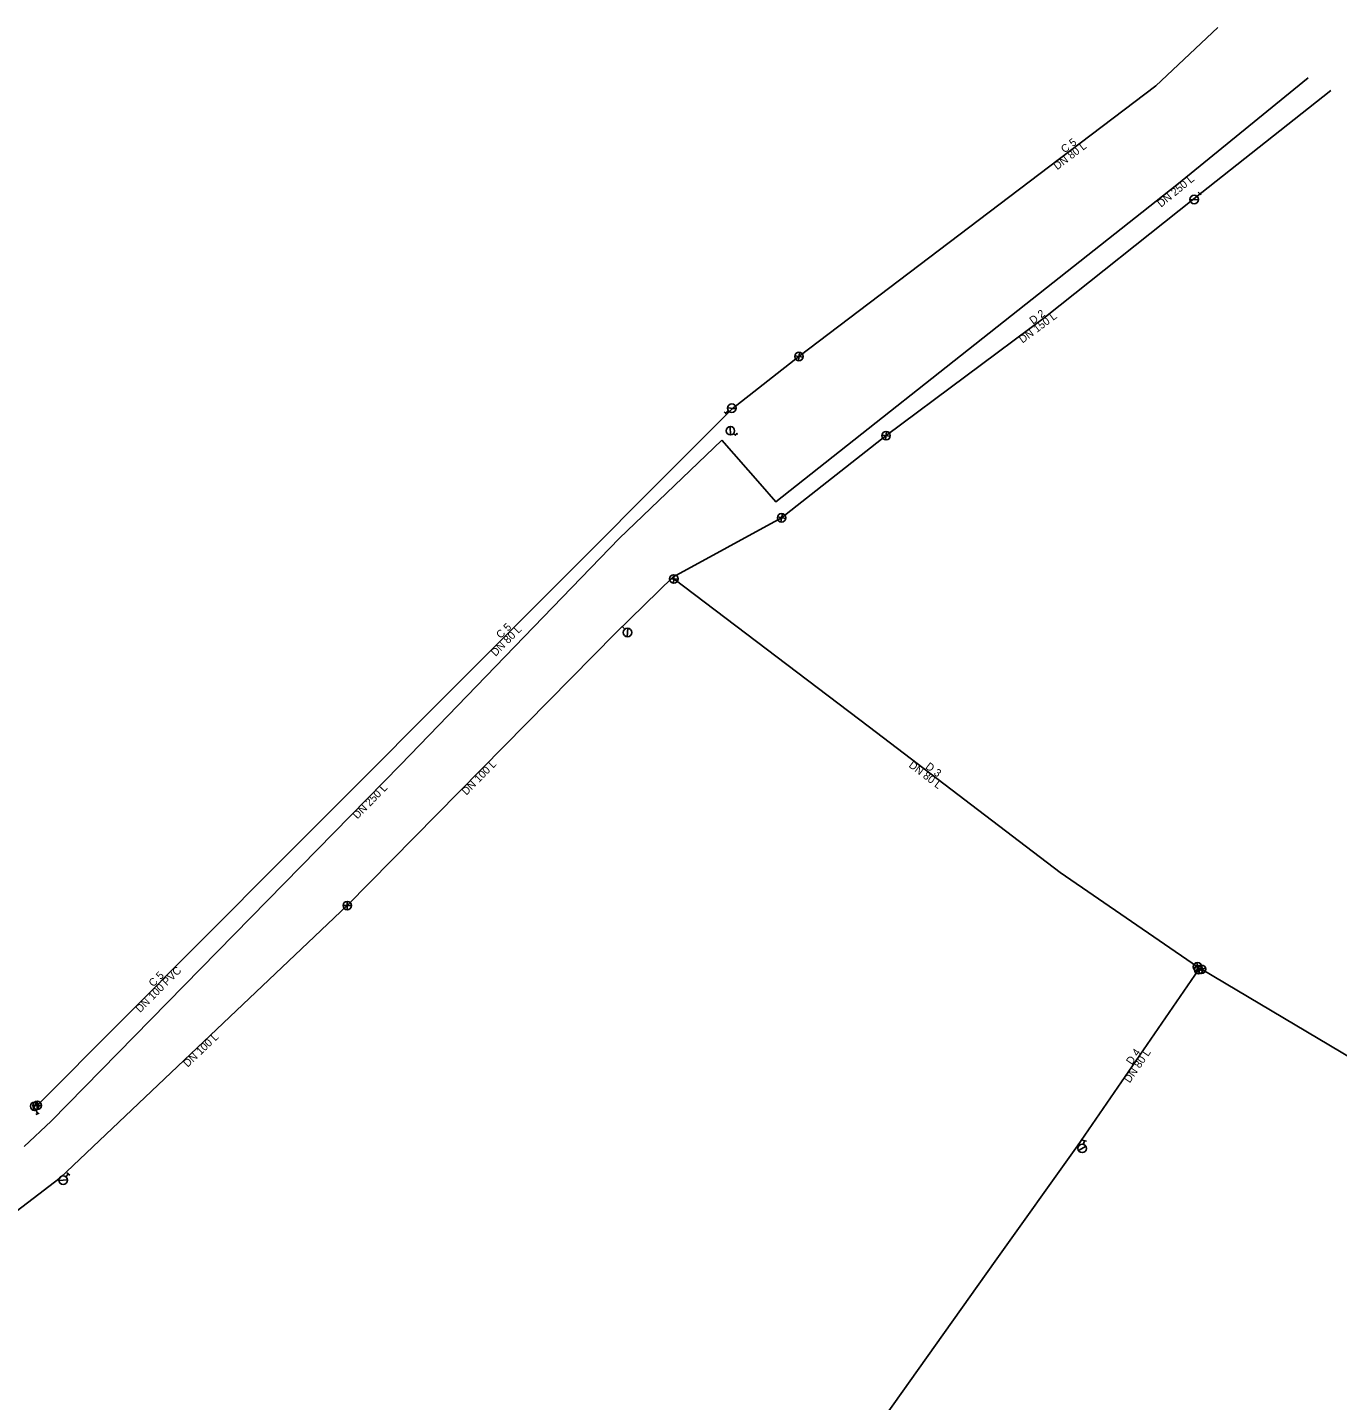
# Model space of a CAD drawing. Extents: x -600635 to -600187, y -1203951 to -1203569.
# Drawn here: x -600453.9 to -600299.8, y -1203730.9 to -1203569.5 of the extents above; entities that cross this region are included whole.
import ezdxf

# ---------------------------------------------------------------- set-up
doc = ezdxf.new("R2010")
doc.units = 0
for name, color, linetype in [('Default', 7, 'Continuous'), ('hydrant_v_majetku_nebo_provozovany', 7, 'Continuous'), ('popisy_rad', 7, 'Continuous'), ('rad_v_majetku', 7, 'Continuous'), ('uzaver_v_majetku_nebo_provozovany', 7, 'Continuous')]:
    doc.layers.add(name, color=color, linetype=linetype)

# ---------------------------------------------------------------- blocks, each defined once
blk = doc.blocks.new('MoSymbol 2')
at = {"layer": 'Default'}
for p, q in [((-0.000035, -0.000035), (0.000035, 0.000035)), ((0.000035, -0.000035), (-0.000035, 0.000035))]:
    blk.add_line(p, q, dxfattribs=at)
for radius in [0.00005, 0.0000025]:
    blk.add_circle((0, 0), radius, dxfattribs=at)
blk = doc.blocks.new('MoSymbol 3')
at = {"layer": 'Default'}
for p, q in [((-0.000036, -0.000036), (0.000036, 0.000036)), ((-0.000023, 0.000095), (0.000023, 0.000095)), ((0, 0.000095), (0, 0.00005))]:
    blk.add_line(p, q, dxfattribs=at)
blk.add_circle((0, 0), 0.00005, dxfattribs=at)
blk = doc.blocks.new('MoSymbol 4')
at = {"layer": 'Default'}
for p, q in [((-0.000036, -0.000036), (0.000036, 0.000036)), ((0.00003, -0.00008), (0.00002, -0.000085))]:
    blk.add_line(p, q, dxfattribs=at)
blk.add_lwpolyline([(0, -0.00005), (0, -0.00008), (0.00003, -0.00008), (0.00002, -0.000075)], dxfattribs=at)
blk.add_circle((0, 0), 0.00005, dxfattribs=at)

msp = doc.modelspace()

# ---------------------------------------------------------------- linework, layer by layer
at = {"layer": 'rad_v_majetku'}
for p, q in [((-600316.71, -1203589.64), (-600300.57, -1203576.9)), ((-600363.13, -1203608.16), (-600370.99, -1203614.29)), ((-600370.99, -1203614.29), (-600423.62, -1203667.02)), ((-600365.17, -1203627.11), (-600352.89, -1203617.46)), ((-600377.98, -1203634.08), (-600365.17, -1203627.11)), ((-600384.65, -1203640.63), (-600377.98, -1203634.08)), ((-600377.85, -1203634.3), (-600377.98, -1203634.08)), ((-600416.25, -1203672.7), (-600384.65, -1203640.63)), ((-600423.62, -1203667.02), (-600452.72, -1203696.18)), ((-600450.01, -1203704.7), (-600416.25, -1203672.7)), ((-600316.13, -1203680.24), (-600330.38, -1203700.93)), ((-600316.02, -1203680.05), (-600316.26, -1203679.89)), ((-600316.02, -1203680.05), (-600316.13, -1203680.24)), ((-600315.79, -1203680.19), (-600316.02, -1203680.05))]:
    msp.add_line(p, q, dxfattribs=at)
for points in [[(-600313.89, -1203569.48), (-600321.18, -1203576.33), (-600332.51, -1203584.93), (-600363.13, -1203608.16)], [(-600303.26, -1203575.4), (-600318.68, -1203587.96), (-600335.72, -1203601.41), (-600365.84, -1203625.25), (-600367.7, -1203623.11), (-600372.22, -1203617.99)], [(-600352.89, -1203617.46), (-600334.15, -1203603.51), (-600316.71, -1203589.64)], [(-600372.22, -1203617.99), (-600384.28, -1203629.56), (-600410.01, -1203656.15), (-600451.09, -1203698.02), (-600454.25, -1203701.01)], [(-600316.26, -1203679.89), (-600332.43, -1203668.79), (-600354.84, -1203651.73), (-600377.85, -1203634.3)], [(-600236.89, -1203728.36), (-600242.38, -1203724.95), (-600264, -1203711.73), (-600288.95, -1203696.47), (-600297.92, -1203690.81), (-600315.79, -1203680.19)], [(-600330.38, -1203700.93), (-600340.06, -1203714.49), (-600360.04, -1203742.64), (-600371.82, -1203758.94), (-600385.69, -1203786.01), (-600395.74, -1203804.12)], [(-600529.07, -1203761.9), (-600506.65, -1203745.16), (-600494.67, -1203737.19), (-600466.59, -1203717.37), (-600450.01, -1203704.7)]]:
    msp.add_lwpolyline(points, dxfattribs=at)

# ---------------------------------------------------------------- block references
at = {"layer": 'hydrant_v_majetku_nebo_provozovany'}
for name, p, xscale, yscale, rotation in [('MoSymbol 3', (-600316.65, -1203589.7), 9998.750156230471, 9998.75015623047, -42.80392229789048), ('MoSymbol 3', (-600371.03, -1203614.23), 9998.75015623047, 9998.750156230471, 128.5630116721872), ('MoSymbol 4', (-600371.2, -1203616.88), 9998.75015623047, 9998.750156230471, 47.66988975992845), ('MoSymbol 3', (-600383.29, -1203640.6), 9998.75015623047, 9998.750156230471, 41.15293018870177), ('MoSymbol 3', (-600453.02, -1203696.29), 9998.75015623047, 9998.750156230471, -159.07019206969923), ('MoSymbol 3', (-600329.82, -1203701.24), 9998.75015623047, 9998.750156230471, -16.440379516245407), ('MoSymbol 3', (-600449.67, -1203704.98), 9998.75015623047, 9998.750156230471, -40.2326517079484)]:
    msp.add_blockref(name, p, dxfattribs=dict(at, xscale=xscale, yscale=yscale, rotation=rotation))
at = {"layer": 'uzaver_v_majetku_nebo_provozovany'}
for p, xscale, yscale, rotation in [((-600363.13, -1203608.16), 9998.75015623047, 9998.750156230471, -142.43906434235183), ((-600352.89, -1203617.46), 9998.750156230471, 9998.75015623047, -142.5887421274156), ((-600365.17, -1203627.11), 9998.750156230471, 9998.75015623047, -146.63737693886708), ((-600377.85, -1203634.3), 9998.75015623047, 9998.750156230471, 132.556395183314), ((-600416.25, -1203672.7), 9998.750156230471, 9998.75015623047, -135.55570801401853), ((-600316.26, -1203679.89), 9998.750156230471, 9998.75015623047, 145.54188289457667), ((-600316.13, -1203680.24), 9998.75015623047, 9998.750156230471, -122.49482217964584), ((-600315.79, -1203680.19), 9998.750156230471, 9998.750156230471, 149.2825871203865), ((-600452.72, -1203696.18), 9998.750156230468, 9998.750156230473, -134.9429196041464)]:
    msp.add_blockref('MoSymbol 2', p, dxfattribs=dict(at, xscale=xscale, yscale=yscale, rotation=rotation))

# ---------------------------------------------------------------- texts
at = {"layer": 'popisy_rad'}
for s, rotation, p in [('C 5', 37.1988, (-600331.9, -1203584.29)), ('DN 80 L', 37.1988, (-600332.77, -1203586.27)), ('DN 250 L', 39.1629, (-600320.55, -1203590.67)), ('DN 150 L', 36.656, (-600336.84, -1203606.64)), ('D 2', 36.656, (-600335.61, -1203604.42)), ('DN 80 L', 45.0571, (-600398.82, -1203643.46)), ('C 5', 45.0571, (-600398.21, -1203641.38)), ('DN 100 L', 45.4202, (-600402.25, -1203659.79)), ('DN 80 L', 322.7138, (-600350.3, -1203656.34)), ('D 3', 322.7138, (-600348.33, -1203656.51)), ('DN 250 L', 45.5415, (-600415.06, -1203662.59)), ('DN 100 PVC', 45.0571, (-600440.61, -1203685.34)), ('C 5', 45.0571, (-600439.07, -1203682.32)), ('DN 100 L', 43.4684, (-600435.03, -1203691.76)), ('DN 80 L', 55.4361, (-600324.24, -1203693.62)), ('D 4', 55.4361, (-600323.99, -1203691.48))]:
    msp.add_text(s, height=0.91, rotation=rotation, dxfattribs=at).set_placement(p)

doc.saveas('drawing.dxf')
